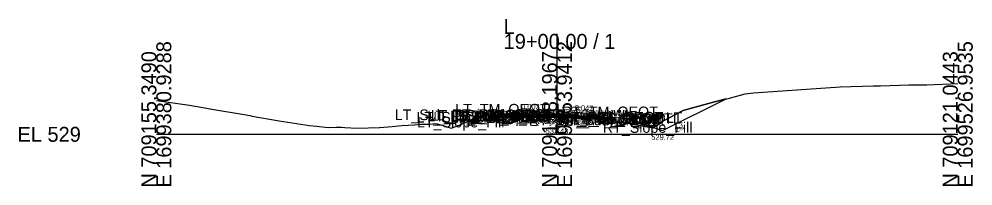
# Model space of a CAD drawing. Extents: x -63 to 1153, y -24 to 9522.
# Drawn here: x 974.3 to 1152.8, y 990.3 to 1021.6 of the extents above; entities that cross this region are included whole.
import ezdxf

# ---------------------------------------------------------------- set-up
doc = ezdxf.new("R2010")
doc.units = 0
for name, color, linetype in [('Default', 7, 'Continuous'), ('Exist Cross Section Cell', 7, 'Continuous'), ('Exist XS Center Line Elevation Label', 7, 'Continuous'), ('Exist XS Ground Line', 7, 'Continuous'), ('Prop CMT DNC', 7, 'Continuous'), ('Prop CMT Pvmt Course 1', 7, 'Continuous'), ('Prop CMT Pvmt Course 2', 7, 'Continuous'), ('Prop CMT Pvmt Surface', 7, 'Continuous'), ('Prop CMT Pvmt Surface Overlay', 7, 'Continuous'), ('Prop CMT Pvmt Surface Shoulder', 7, 'Continuous'), ('Prop CMT Shld Paved Course 1', 7, 'Continuous'), ('Prop CMT Shld Paved Course 2', 7, 'Continuous'), ('Prop CMT Slope Grass', 7, 'Continuous'), ('Prop CMT Subgrade Earthwork', 7, 'Continuous'), ('Prop XS Ditch Standard Text', 7, 'Continuous'), ('Prop XS Earthwork Shape', 7, 'Continuous'), ('Prop XS EOT Tick Mark', 7, 'Continuous'), ('Prop XS SE Text', 7, 'Continuous'), ('Prop XS Side Slope Text', 7, 'Continuous')]:
    doc.layers.add(name, color=color, linetype=linetype)

msp = doc.modelspace()

# ---------------------------------------------------------------- linework, layer by layer
at = {"layer": 'Exist Cross Section Cell'}
for p, q in [((1075, 1000), (1075, 1018.84)), ((1000, 1000), (1075, 1000)), ((1075, 1000), (1150, 1000))]:
    msp.add_line(p, q, dxfattribs=at)
at = {"layer": 'Exist XS Ground Line'}
msp.add_lwpolyline([(1000, 1006.32), (1006.22, 1005.45), (1008.69, 1005.04), (1010.36, 1004.75), (1016.43, 1003.71), (1017.48, 1003.54), (1017.91, 1003.43), (1023, 1002.56), (1027.84, 1001.76), (1028.69, 1001.66), (1029.97, 1001.53), (1032.16, 1001.31), (1033.68, 1001.34), (1034.64, 1001.32), (1035.25, 1001.31), (1037.6, 1001.18), (1041.77, 1001.31), (1041.78, 1001.31), (1041.79, 1001.31), (1041.81, 1001.31), (1041.83, 1001.31), (1044.16, 1001.49), (1045.97, 1001.63), (1048.31, 1001.79), (1049.52, 1001.88), (1051.05, 1001.9), (1052.32, 1002.01), (1053.27, 1001.75), (1055.18, 1001.17), (1056.08, 1001.44), (1057.97, 1002.27), (1059.41, 1002.4), (1065.19, 1003.33), (1070.67, 1003.4), (1075, 1003.43), (1075.02, 1003.43), (1080.49, 1003.04), (1084.58, 1002.74), (1088.16, 1002.08), (1089.1, 1001.9), (1092.53, 1001.3), (1093, 1001.22), (1093.29, 1001.45), (1093.73, 1001.71), (1094.81, 1002.49), (1098.48, 1004.41), (1098.63, 1004.48), (1099.46, 1004.73), (1104.72, 1006.17), (1107.26, 1006.81), (1110.21, 1007.61), (1111.8, 1007.79), (1128.02, 1008.9), (1134.25, 1009.08), (1135.54, 1009.12), (1140.84, 1009.28), (1144.22, 1009.26), (1150, 1009.55)], dxfattribs=at)
at = {"layer": 'Prop CMT Pvmt Course 1'}
for points in [[(1075, 1003.69), (1065, 1003.71)], [(1065, 1003.71), (1065, 1003.46)], [(1065, 1003.46), (1075, 1003.44)], [(1075, 1003.56), (1075, 1003.69)], [(1075, 1003.69), (1085, 1003.21)], [(1075, 1003.56), (1075, 1003.69)], [(1075, 1003.44), (1075, 1003.56), (1075, 1003.56)], [(1075, 1003.44), (1075, 1003.56), (1075, 1003.56)], [(1085, 1002.96), (1075, 1003.44)], [(1085, 1003.21), (1085, 1002.96)]]:
    msp.add_lwpolyline(points, dxfattribs=at)
at = {"layer": 'Prop CMT Pvmt Course 2'}
for points in [[(1075, 1003.44), (1065, 1003.46)], [(1065, 1003.46), (1065, 1003.21)], [(1075, 1003.19), (1075, 1003.44)], [(1075, 1003.19), (1075, 1003.44)], [(1075, 1003.44), (1085, 1002.96)], [(1065, 1003.21), (1075, 1003.19)], [(1085, 1002.71), (1075, 1003.19)], [(1085, 1002.96), (1085, 1002.71)]]:
    msp.add_lwpolyline(points, dxfattribs=at)
at = {"layer": 'Prop CMT Pvmt Surface'}
for points in [[(1075, 1003.69), (1065, 1003.71)], [(1075, 1003.69), (1085, 1003.21)]]:
    msp.add_lwpolyline(points, dxfattribs=at)
at = {"layer": 'Prop CMT Pvmt Surface Overlay'}
for points in [[(1075, 1003.69), (1065, 1003.71)], [(1075, 1003.69), (1085, 1003.21)]]:
    msp.add_lwpolyline(points, dxfattribs=at)
at = {"layer": 'Prop CMT Pvmt Surface Shoulder'}
for points in [[(1065, 1003.71), (1064.99, 1003.71)], [(1085, 1003.21), (1085.01, 1003.21)]]:
    msp.add_lwpolyline(points, dxfattribs=at)
at = {"layer": 'Prop CMT Shld Paved Course 1'}
for points in [[(1065, 1003.71), (1064.99, 1003.71), (1064.74, 1003.46)], [(1064.74, 1003.46), (1065, 1003.46)], [(1065, 1003.46), (1065, 1003.71)], [(1085, 1003.21), (1085.01, 1003.21), (1085.27, 1002.95)], [(1085, 1002.96), (1085, 1003.21)], [(1085.27, 1002.95), (1085, 1002.96)]]:
    msp.add_lwpolyline(points, dxfattribs=at)
at = {"layer": 'Prop CMT Shld Paved Course 2'}
for points in [[(1064.74, 1003.46), (1064.49, 1003.21)], [(1065, 1003.46), (1064.74, 1003.46)], [(1064.74, 1003.46), (1064.74, 1003.46)], [(1065, 1003.21), (1065, 1003.46)], [(1064.49, 1003.21), (1065, 1003.21)], [(1085, 1002.96), (1085.27, 1002.95)], [(1085, 1002.71), (1085, 1002.96)], [(1085.53, 1002.69), (1085, 1002.71)], [(1085.27, 1002.95), (1085.27, 1002.95)], [(1085.27, 1002.95), (1085.53, 1002.69)]]:
    msp.add_lwpolyline(points, dxfattribs=at)
at = {"layer": 'Prop CMT Slope Grass'}
for points in [[(1088, 1002.97), (1094.76, 1000.72), (1106.63, 1006.65)], [(1062, 1003.54), (1058.27, 1002.3)], [(1064.99, 1003.71), (1062, 1003.54)], [(1085, 1003.21), (1088, 1002.97)]]:
    msp.add_lwpolyline(points, dxfattribs=at)
at = {"layer": 'Prop CMT Subgrade Earthwork'}
for points in [[(1064.49, 1003.21), (1064.05, 1003.66)], [(1065, 1003.21), (1064.49, 1003.21)], [(1075, 1003.19), (1065, 1003.21)], [(1075, 1003.19), (1085, 1002.71)], [(1085, 1002.71), (1085.53, 1002.69)], [(1085.53, 1002.69), (1085.98, 1003.13)]]:
    msp.add_lwpolyline(points, dxfattribs=at)
at = {"layer": 'Prop XS Earthwork Shape'}
for points in [[(1093.08, 1001.28), (1094.76, 1000.72), (1106.63, 1006.65), (1104.72, 1006.17), (1099.46, 1004.73), (1098.63, 1004.48), (1098.48, 1004.41), (1094.81, 1002.49), (1093.73, 1001.71), (1093.29, 1001.45)], [(1062, 1003.54), (1058.27, 1002.3), (1059.41, 1002.4), (1064.49, 1003.21), (1064.05, 1003.66)], [(1075, 1003.19), (1065, 1003.21), (1064.49, 1003.21), (1065.19, 1003.33), (1070.67, 1003.4), (1075, 1003.43), (1075.02, 1003.43), (1080.49, 1003.04), (1084.58, 1002.74), (1084.65, 1002.73)], [(1085, 1002.71), (1085.53, 1002.69), (1085.98, 1003.13), (1088, 1002.97), (1093.08, 1001.28), (1093, 1001.22), (1092.53, 1001.3), (1089.1, 1001.9), (1088.16, 1002.08), (1084.65, 1002.73)]]:
    msp.add_lwpolyline(points, close=True, dxfattribs=at)
at = {"layer": 'Prop XS EOT Tick Mark'}
for points in [[(1065, 1003.71), (1065, 1004.71)], [(1085, 1003.21), (1085, 1004.21)]]:
    msp.add_lwpolyline(points, dxfattribs=at)

# ---------------------------------------------------------------- texts
at = {"layer": 'Default'}
msp.add_text('-', height=0.0001, dxfattribs=at).set_placement((1000, 1000))
at = {"layer": 'Exist Cross Section Cell'}
for s, p in [('L', (1065, 1018.84)), ('19+00.00 / 1', (1065, 1016.04)), ('EL 529', (974, 998.6))]:
    msp.add_text(s, height=2.8, dxfattribs=at).set_placement(p)
for s, p in [('E 1699380.9288', (1002.8, 990)), ('E 1699453.9412', (1077.8, 990)), ('E 1699526.9535', (1152.8, 990)), ('N 709155.3490', (1000, 990)), ('N 709138.1967', (1075, 990)), ('N 709121.0443', (1150, 990))]:
    msp.add_text(s, height=2.8, rotation=90, dxfattribs=at).set_placement(p)
at = {"layer": 'Exist XS Center Line Elevation Label'}
msp.add_text('532.43', height=1, dxfattribs=at).set_placement((1072.88, 1000.1))
at = {"layer": 'Prop CMT DNC'}
for s, p in [('LT_TM_OEOT', (1055.94, 1003.71)), ('RT_TM_OEOT', (1075.9, 1003.21)), ('LT_Sub_Trench_Out_DLT', (1044.61, 1002.66)), ('LT_Sub_Trench_Out', (1048.7, 1002.21)), ('LT_Slope_Fill', (1048.79, 1001.3)), ('LT_PS2_Shelf_Out', (1050.72, 1002.46)), ('LT_GS_OS_CTL', (1051.37, 1002.54)), ('LT_PS2_OEOP', (1054.98, 1002.46)), ('LT_Sub_OEOT', (1055.08, 1002.21)), ('LT_PV2_OEOT', (1055.17, 1002.46)), ('LT_PV1_OEOT', (1055.74, 1002.71)), ('LT_PS1_OEOP', (1055.79, 1002.71)), ('RT_PV1_OEEOP_W', (1062.94, 1002.56)), ('LT_PV1_OEEOP_W', (1062.98, 1002.56)), ('RT_Sub_OEEOP', (1064.17, 1002.19)), ('LT_Sub_OEEOP', (1064.21, 1002.19)), ('RT_PV2_OEEOP', (1064.26, 1002.44)), ('LT_PV2_OEEOP', (1064.31, 1002.44)), ('RT_Sub_Trench_Out_DLT', (1066.5, 1002.13)), ('PV1_PGL_W', (1067.58, 1002.56)), ('PV1_PGL', (1069.47, 1002.69)), ('RT_Sub_Trench_Out', (1069.69, 1001.69)), ('RT_PS2_Shelf_Out', (1071.21, 1001.95)), ('RT_Sub_OEOT', (1075.03, 1001.71)), ('RT_PV2_OEOT', (1075.13, 1001.96)), ('RT_PS2_OEOP', (1075.46, 1001.95)), ('RT_PV1_OEOT', (1075.69, 1002.21)), ('RT_PS1_OEOP', (1075.77, 1002.21)), ('RT_GS_OS_CTL', (1077.32, 1001.97)), ('RT_Slope_Fill', (1083.55, 1000.28))]:
    msp.add_text(s, height=2, dxfattribs=at).set_placement(p)
at = {"layer": 'Prop XS Ditch Standard Text'}
msp.add_text('529.72', height=1, dxfattribs=at).set_placement((1092.66, 998.97))
at = {"layer": 'Prop XS SE Text'}
for s, rotation, p in [('0.002', 359.8568, (1068.29, 1004.7)), ('0.047', 357.2841, (1078.3, 1004.53))]:
    msp.add_text(s, height=1, rotation=rotation, dxfattribs=at).set_placement(p)
at = {"layer": 'Prop XS Side Slope Text'}
for s, rotation, p in [('3:1', 18.4332, (1059.15, 1003.38)), ('3:1', 341.5652, (1090.03, 1003.09)), ('2:1', 26.5651, (1097.36, 1000.31))]:
    msp.add_text(s, height=1, rotation=rotation, dxfattribs=at).set_placement(p)

doc.saveas('drawing.dxf')
